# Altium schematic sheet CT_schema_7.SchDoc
size 371 x 245 mm
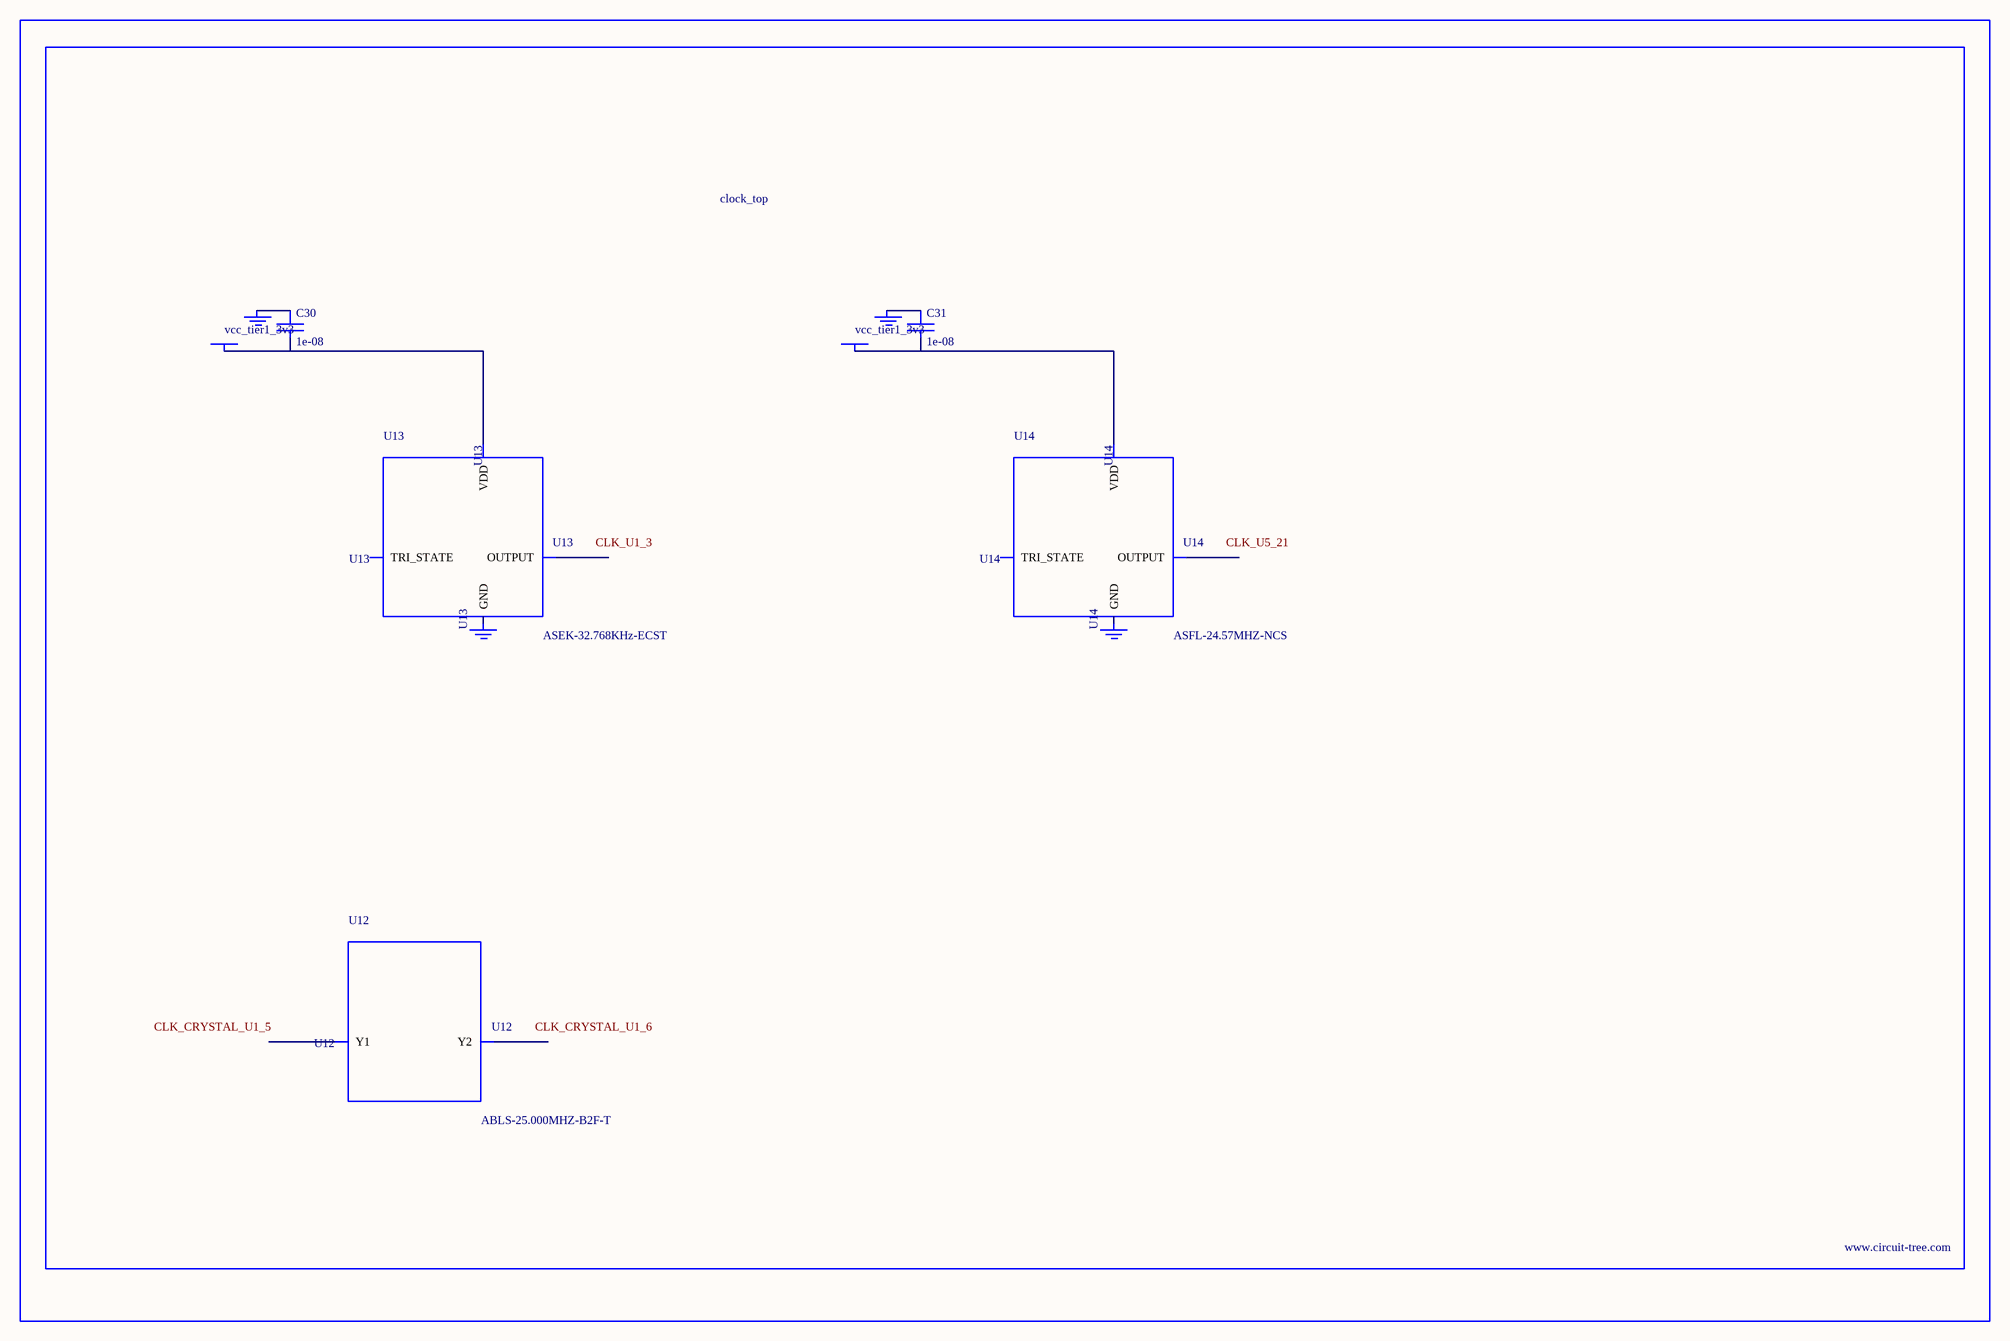
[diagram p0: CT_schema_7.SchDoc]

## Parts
BORDER6  (no value)
C30  1e-08  [C0402]
C31  1e-08  [C0402]
GND_INSTANCE_6_0  (no value)
GND_INSTANCE_6_1  (no value)
GND_INSTANCE_6_2  (no value)
GND_INSTANCE_6_3  (no value)
POWER_INSTANCE_6_0  vcc_tier1_3v3
POWER_INSTANCE_6_1  vcc_tier1_3v3
U12  ABLS-25.000MHZ-B2F-T  [ABLS-25.000MHZ-B2F-T]
U13  ASEK-32.768KHz-ECST  [ASEK]
U14  ASFL-24.57MHZ-NCS  [ASFL1]

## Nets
NetC30_1: C30.1 GND_INSTANCE_6_0.0(GND)
NetC30_2: C30.2 POWER_INSTANCE_6_0.0(PWR) U13.4(VDD)
NetC31_1: C31.1 GND_INSTANCE_6_2.0(GND)
NetC31_2: C31.2 POWER_INSTANCE_6_1.0(PWR) U14.4(VDD)

Not connected (* = marked no-connect by the designer): GND_INSTANCE_6_1 0(GND); GND_INSTANCE_6_3 0(GND); U12 1(Y1) 2(Y2); U13 1(TRI_STATE) 2(GND) 3(OUTPUT); U14 1(TRI_STATE) 2(GND) 3(OUTPUT)

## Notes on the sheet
- Labels drawn without touching a wire or pin: CLK_CRYSTAL_U1_5, CLK_CRYSTAL_U1_6, CLK_U1_3, CLK_U5_21

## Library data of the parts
BORDER6 = BORDER_PAGE6
C30 C31 = C0402C103K3RAC
GND_INSTANCE_6_0-GND_INSTANCE_6_3 = GND
POWER_INSTANCE_6_0 POWER_INSTANCE_6_1 = PWR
